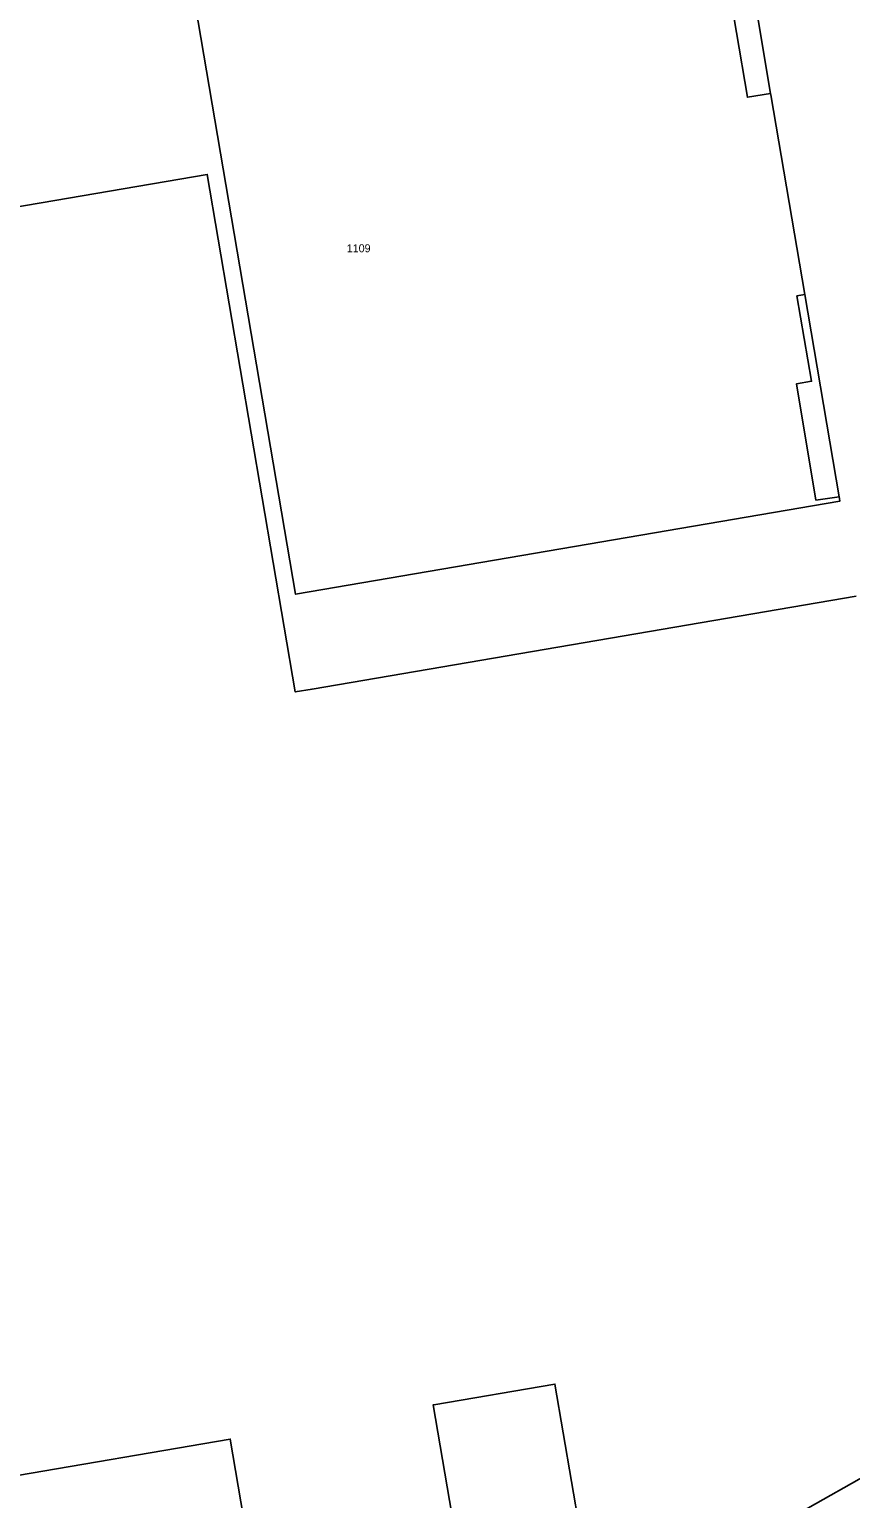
# Model space of a CAD drawing. Extents: x 154324 to 155744, y 382937 to 384188.
# Drawn here: x 154819.6 to 154922.2, y 383179.9 to 383363.4 of the extents above; entities that cross this region are included whole.
import ezdxf

# ---------------------------------------------------------------- set-up
doc = ezdxf.new("R2010")
doc.units = 0
for name, color, linetype in [('IMGEO_Erf', 7, 'Continuous'), ('IMGEO_Pand', 7, 'Continuous'), ('IMGEO_Pand_nummerreeks', 7, 'Continuous'), ('IMGEO_Pand_overbouw', 7, 'Continuous')]:
    doc.layers.add(name, color=color, linetype=linetype)

msp = doc.modelspace()

# ---------------------------------------------------------------- linework, layer by layer
at = {"layer": 'IMGEO_Erf'}
msp.add_lwpolyline([(154838.62, 383376.66), (154906.67, 383388.27), (154909.47, 383371.88), (154909.51, 383371.67), (154906.59, 383371.18), (154909.35, 383354.96), (154912.25, 383355.45), (154912.29, 383355.25), (154916.53, 383330.32), (154915.54, 383330.14), (154917.36, 383319.49), (154915.46, 383319.16), (154917.9, 383304.64), (154920.82, 383305.04), (154920.86, 383304.83), (154920.91, 383304.51), (154852.88, 383292.89)], close=True, dxfattribs=at)
for points in [[(154773.95, 383333.72), (154841.85, 383345.32), (154852.85, 383280.68), (154854.94, 383281.04), (154922.94, 383292.64)], [(154925.91, 383183.81), (154890.47, 383163.81), (154885.3, 383194.22), (154870.15, 383191.64), (154870.08, 383191.63), (154876.19, 383155.75)], [(154852.39, 383142.32), (154844.72, 383187.34), (154788.11, 383177.68)]]:
    msp.add_lwpolyline(points, dxfattribs=at)
at = {"layer": 'IMGEO_Pand'}
msp.add_lwpolyline([(154838.62, 383376.66), (154852.88, 383292.89), (154920.91, 383304.51), (154920.86, 383304.83), (154920.82, 383305.04), (154917.9, 383304.64), (154915.46, 383319.16), (154917.36, 383319.49), (154915.54, 383330.14), (154916.53, 383330.32), (154912.29, 383355.25), (154912.25, 383355.45), (154909.35, 383354.96), (154906.59, 383371.18), (154909.51, 383371.67), (154909.47, 383371.88), (154906.67, 383388.27)], close=True, dxfattribs=at)
for points in [[(154922.94, 383292.64), (154854.94, 383281.04), (154852.85, 383280.68), (154841.85, 383345.32), (154773.95, 383333.72)], [(154876.19, 383155.75), (154870.08, 383191.63), (154870.15, 383191.64), (154885.3, 383194.22), (154890.47, 383163.81), (154925.91, 383183.81)], [(154788.11, 383177.68), (154844.72, 383187.34), (154852.39, 383142.32)]]:
    msp.add_lwpolyline(points, dxfattribs=at)
at = {"layer": 'IMGEO_Pand_overbouw'}
for points in [[(154909.51, 383371.67), (154906.59, 383371.18), (154909.35, 383354.96), (154912.25, 383355.45)], [(154916.53, 383330.32), (154915.54, 383330.14), (154917.36, 383319.49), (154915.46, 383319.16), (154917.9, 383304.64), (154920.82, 383305.04)]]:
    msp.add_lwpolyline(points, close=True, dxfattribs=at)

# ---------------------------------------------------------------- texts
at = {"layer": 'IMGEO_Pand_nummerreeks'}
msp.add_text('1109', height=1, dxfattribs=at).set_placement((154859.28, 383335.6))

doc.saveas('drawing.dxf')
